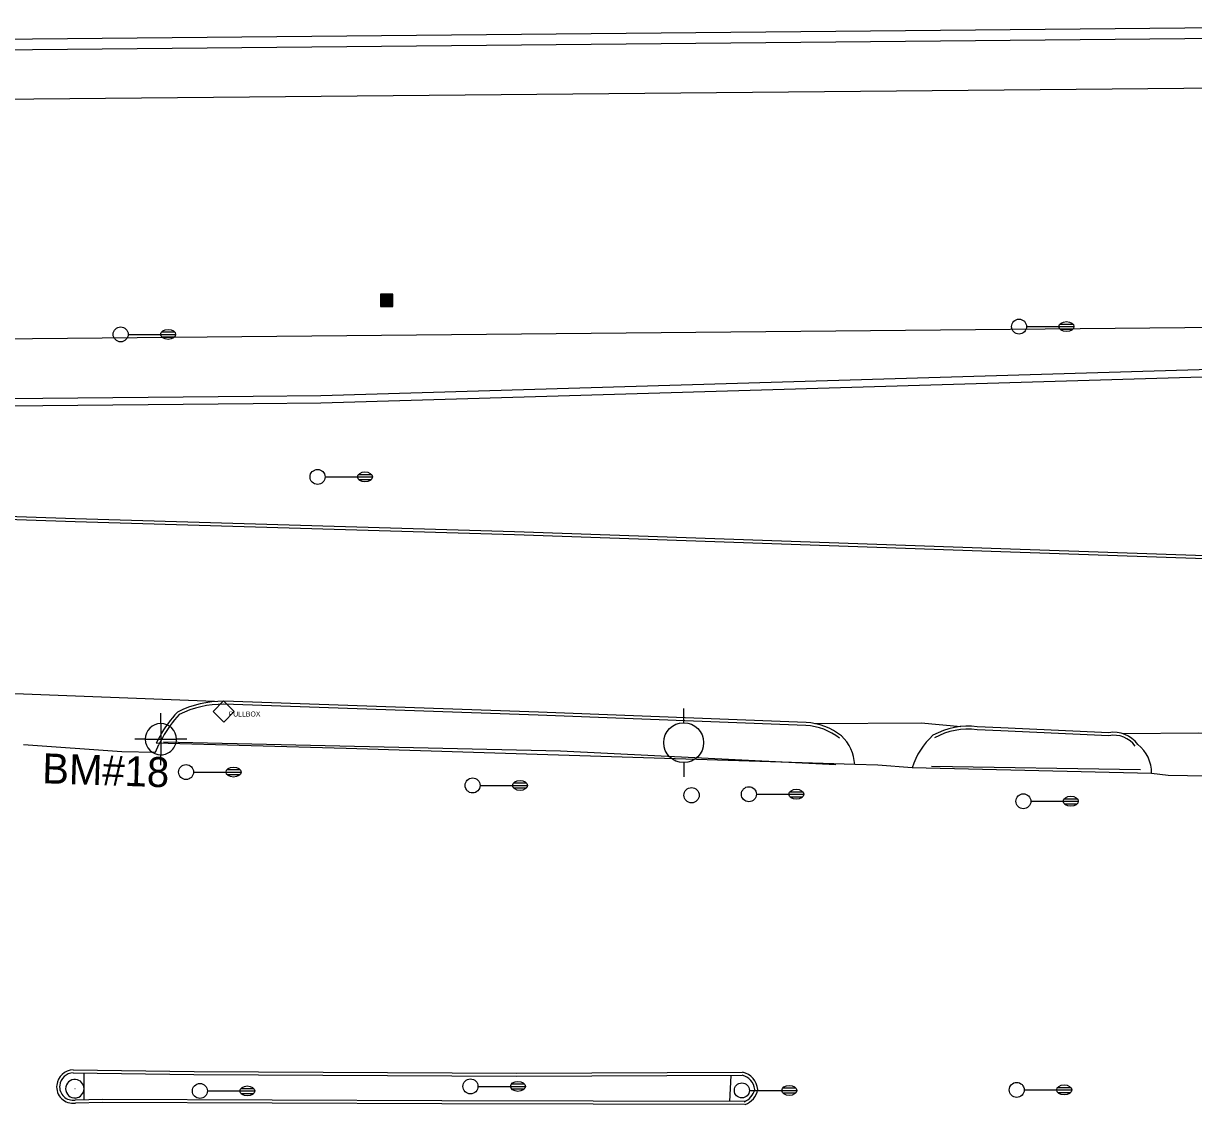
# Model space of a CAD drawing. Extents: x 2145380 to 2157287, y 139568 to 149130.
# Drawn here: x 2146909.1 to 2147143.4, y 142843.8 to 143060.4 of the extents above; entities that cross this region are included whole.
import ezdxf

# ---------------------------------------------------------------- set-up
doc = ezdxf.new("R2010")
doc.units = 0
for name, color, linetype in [('Default', 7, 'Continuous'), ('PR_PREVIOUSLY CONSTRUCTED', 7, 'Continuous'), ('SURV_Benchmark', 7, 'Continuous'), ('TOPO_Asphalt', 7, 'Continuous'), ('TOPO_Concrete', 7, 'Continuous'), ('TOPO_Curb Back', 7, 'Continuous'), ('TOPO_Guardrail', 7, 'Continuous'), ('TOPO_Light Pole', 7, 'Continuous'), ('TOPO_Misc', 7, 'Continuous'), ('TOPO_Power Pole', 7, 'Continuous'), ('TOPO_Power Pullbox', 7, 'Continuous'), ('TOPO_Water Meter', 7, 'Continuous')]:
    doc.layers.add(name, color=color, linetype=linetype)

# ---------------------------------------------------------------- blocks, each defined once
blk = doc.blocks.new('CB')
at = {"layer": 'TOPO_Misc'}
for p, q in [((-3.08, 2.99), (3.24, 2.99)), ((-3.08, 2.68), (3.24, 2.68)), ((-3.08, 2.36), (3.24, 2.36)), ((-3.08, 2.05), (3.24, 2.05)), ((-3.08, 1.73), (3.24, 1.73)), ((-3.08, 1.4), (3.24, 1.4)), ((-3.08, 1.1), (3.24, 1.1)), ((-3.08, 0.77), (3.24, 0.77)), ((-3.08, 0.46), (3.24, 0.46)), ((-3.08, 0.14), (3.24, 0.14)), ((-3.08, -0.17), (3.24, -0.17)), ((-3.08, -0.48), (3.24, -0.48)), ((-3.08, -0.8), (3.24, -0.8)), ((-3.08, -1.11), (3.26, -1.11)), ((-3.08, -1.43), (3.26, -1.43)), ((-3.08, -1.75), (3.26, -1.75)), ((-3.08, -2.07), (3.26, -2.07)), ((-3.08, -2.39), (3.26, -2.39)), ((-3.08, -2.7), (3.26, -2.7)), ((-3.08, -3.02), (3.26, -3.02))]:
    blk.add_line(p, q, dxfattribs=at)
blk.add_lwpolyline([(3.26, -3.29), (3.24, 3.05), (-3.09, 3.04), (-3.08, -3.3), (3.26, -3.29)], dxfattribs=at)
blk = doc.blocks.new('LP')
at = {"layer": 'TOPO_Light Pole'}
blk.add_line((3.81, 0), (20.32, 0), dxfattribs=at)
for points in [[(20.32, 0), (27.94, 0)], [(20.32, 0), (23.5, 0)], [(20.83, 1.27), (27.43, 1.27)], [(20.83, 1.27), (23.5, 1.27)], [(23.71, 1.27), (27.43, 1.27)], [(23.71, 0), (27.94, 0)], [(20.83, -1.27), (27.43, -1.27)], [(20.83, -1.27), (23.5, -1.27)], [(23.71, -1.27), (27.43, -1.27)]]:
    blk.add_lwpolyline(points, dxfattribs=at)
blk.add_circle((0, 0), 3.81, dxfattribs=at)
blk.add_ellipse((24.13, 0), major_axis=(3.81, 0), ratio=0.666667, dxfattribs=at)
blk = doc.blocks.new('POWPOL')
at = {"layer": 'TOPO_Power Pole'}
for p, q in [((0, 10.16), (0, 17.34)), ((0, -10.16), (0, -17.34))]:
    blk.add_line(p, q, dxfattribs=at)
blk.add_circle((0, 0), 10.16, dxfattribs=at)
blk = doc.blocks.new('pulbox')
at = {"layer": 'Default'}
blk.add_lwpolyline([(-5.38, -0.01), (-0.02, 5.42), (5.4, 0.06), (0.05, -5.36), (-5.38, -0.01)], dxfattribs=at)
blk.add_text('PULLBOX', height=2.54, dxfattribs=at).set_placement((2.54, -2.54))
blk = doc.blocks.new('WTRMTR')
at = {"layer": 'Default'}
blk.add_circle((0, 0), 3.89, dxfattribs=at)
blk = doc.blocks.new('BM')
at = {"layer": 'SURV_Benchmark'}
for p, q in [((0, 2.49), (0, 4.15)), ((-2.49, 0), (-4.16, 0)), ((4.16, 0), (2.49, 0)), ((0, -4.16), (0, -2.49))]:
    blk.add_line(p, q, dxfattribs=at)
for points in [[(0, 2.49), (0, 2.49), (0, 0), (2.49, 0), (2.49, 0), (2.49, 0)], [(0, 2.49), (0, 2.49), (0, 0), (2.49, 0), (2.49, 0), (2.49, 0), (2.49, 0)], [(-2.5, 0), (-2.49, 0), (0, 0), (0, -2.49), (0, -2.49)], [(-2.5, 0), (-2.49, 0), (0, 0), (0, -2.49), (0, -2.49)]]:
    blk.add_lwpolyline(points, dxfattribs=at)
for start, end in [(90.0638, 180.0068), (0.0638, 90.0068), (0.0638, 90.0068), (180.0638, 270.0068), (180.0638, 270.0068), (269.9472, 359.9927)]:
    blk.add_arc((0, 0), 2.5, start, end, dxfattribs=at)

msp = doc.modelspace()

# ---------------------------------------------------------------- linework, layer by layer
at = {"layer": 'PR_PREVIOUSLY CONSTRUCTED'}
for p, q in [((2146771.97, 143056.01), (2147234.91, 143060.39)), ((2146771.99, 143053.88), (2147234.93, 143058.27)), ((2146054.19, 143037.14), (2147732.71, 143053.05)), ((2146653.08, 142994.81), (2148008.49, 143007.66))]:
    msp.add_line(p, q, dxfattribs=at)
for points in [[(2148008.6, 142995.66), (2147788.63, 142993.58), (2147488.58, 142996.73), (2147268.56, 142994.65), (2146968.63, 142985.8), (2146955.12, 142985.68), (2146653.19, 142982.81)], [(2147265.03, 142993.04), (2146968.66, 142984.3), (2146955.13, 142984.18), (2146653.2, 142981.31)]]:
    msp.add_lwpolyline(points, dxfattribs=at)
at = {"layer": 'TOPO_Asphalt'}
msp.add_line((2146947.37, 142924.52), (2146896.22, 142926.49), dxfattribs=at)
for points in [[(2147067.59, 142920.13), (2147088.88, 142920.25), (2147096.8, 142919.53)], [(2147075.57, 142911.9), (2147043.9, 142912.93), (2146973.74, 142915.13), (2146935.71, 142916.19)], [(2147129.27, 142918.11), (2147144.44, 142918.24), (2147156.91, 142917.19)], [(2146909.1, 142915.9), (2146928.83, 142914.53), (2146935.54, 142914.42), (2146936.25, 142915.92)], [(2147087.06, 142911.28), (2147080.22, 142911.76), (2147075.57, 142911.9)], [(2147135, 142910.15), (2147087.06, 142911.28)], [(2147146.08, 142909.6), (2147138.37, 142909.71), (2147135, 142910.15)]]:
    msp.add_lwpolyline(points, dxfattribs=at)
for centre, radius, start, end in [((2147067.36, 142911.59), 8.21, 2.1983, 47.5517), ((2147101.38, 142906.65), 15.05, 132.3381, 162.0745), ((2147127.91, 142910.3), 7.1, 358.7645, 52.4035)]:
    msp.add_arc(centre, radius, start, end, dxfattribs=at)
at = {"layer": 'TOPO_Concrete'}
for p, q in [((2146921.25, 142844.73), (2146921.25, 142850.11)), ((2147050.57, 142844.4), (2147050.83, 142849.65))]:
    msp.add_line(p, q, dxfattribs=at)
at = {"layer": 'TOPO_Curb Back'}
for points in [[(2147302.2, 142947.89), (2147268.65, 142949.31), (2147196.44, 142951.96), (2147104.86, 142955.1), (2147007.45, 142958.52), (2146919.46, 142961.11), (2146829.72, 142964.19), (2146749.05, 142964.32), (2146671.05, 142963.99)], [(2147302.21, 142947.29), (2147268.63, 142948.71), (2147196.42, 142951.36), (2147104.83, 142954.5), (2147007.43, 142957.92), (2146919.44, 142960.51), (2146829.71, 142963.59), (2146749.05, 142963.72), (2146671.37, 142963.39)], [(2147065.81, 142919.74), (2147012.19, 142921.79), (2146949.24, 142923.99)], [(2147065.84, 142920.34), (2147012.22, 142922.39), (2146949.25, 142924.59)], [(2147126.49, 142917.69), (2147104.82, 142918.65), (2147100.06, 142918.9)], [(2147126.45, 142918.3), (2147104.85, 142919.25), (2147100.11, 142919.5)], [(2146936.4, 142917.56), (2146935.71, 142916.19)], [(2146936.93, 142917.28), (2146936.25, 142915.92)], [(2146919.09, 142850.73), (2146943.27, 142850.42), (2147007.84, 142850.06), (2147053.13, 142850.26)], [(2146919.1, 142850.13), (2146943.26, 142849.82), (2147007.84, 142849.46), (2147053.06, 142849.66)], [(2147053.51, 142844.39), (2146992.92, 142844.57), (2146924.95, 142844.78), (2146919.45, 142844.7)], [(2147053.5, 142843.79), (2146992.91, 142843.97), (2146924.95, 142844.18), (2146919.51, 142844.11)]]:
    msp.add_lwpolyline(points, dxfattribs=at)
for centre, radius, start, end in [((2146949.07, 142904.1), 20.49, 89.478, 116.4721), ((2146949.07, 142904.1), 19.89, 89.5, 116.1521), ((2146959.07, 142904.89), 25.97, 137.48, 150.8017), ((2146959.07, 142904.89), 25.37, 137.7318, 150.7744), ((2147065.25, 142908.17), 11.58, 51.0762, 87.228), ((2147065.25, 142908.17), 12.18, 51.0762, 87.2425), ((2147098.31, 142905.05), 14.56, 82.8845, 119.0455), ((2147098.31, 142905.05), 13.96, 82.7954, 119.0455), ((2147127.49, 142912.6), 5.79, 34.9864, 100.3823), ((2147127.49, 142912.6), 5.19, 34.9864, 101.1114), ((2146919.14, 142847.35), 3.38, 90.8122, 173.7639), ((2146919.14, 142847.35), 2.78, 90.9726, 173.8329), ((2147052.33, 142846.51), 3.23, 6.012, 76.8575), ((2147052.33, 142846.51), 3.83, 4.6307, 77.955), ((2146919.02, 142847.33), 3.26, 173.125, 278.6358), ((2146919.02, 142847.33), 2.66, 173.0531, 279.4792), ((2147052.27, 142847.51), 3.34, 289.857, 348.5009), ((2147052.27, 142847.51), 3.94, 289.857, 349.8401)]:
    msp.add_arc(centre, radius, start, end, dxfattribs=at)
at = {"layer": 'TOPO_Guardrail'}
msp.add_line((2147090.95, 142911.58), (2147132.81, 142910.95), dxfattribs=at)
msp.add_lwpolyline([(2146937.18, 142916.46), (2147016.66, 142914.65), (2147071.79, 142911.92)], dxfattribs=at)
at = {"layer": 'TOPO_Misc'}
for q in [(2146919.42, 142846.95), (2146919.44, 142846.96), (2146919.44, 142846.93), (2146919.45, 142846.95)]:
    msp.add_line((2146919.44, 142846.95), q, dxfattribs=at)
for centre, radius, start, end in [((2146919.43, 142846.98), 1.87, 85.9623, 180), ((2146919.36, 142846.98), 1.88, 276.2662, 83.7338), ((2146919.43, 142846.98), 1.87, 180, 274.0377)]:
    msp.add_arc(centre, radius, start, end, dxfattribs=at)

# ---------------------------------------------------------------- block references
at = {"layer": 'SURV_Benchmark', "xscale": 1.25, "yscale": 1.25}
msp.add_blockref('BM', (2146936.62, 142916.99), dxfattribs=at)
at = {"layer": 'TOPO_Light Pole', "xscale": 0.39370000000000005, "yscale": 0.3937000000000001}
for p in [(2147108.48, 142999.65), (2146928.58, 142998.1), (2146968, 142969.54), (2146941.68, 142910.41), (2146999.05, 142907.73), (2147054.38, 142905.97), (2147109.34, 142904.56), (2146998.63, 142847.44), (2147108.02, 142846.74), (2146944.44, 142846.52), (2147052.97, 142846.63)]:
    msp.add_blockref('LP', p, dxfattribs=at)
at = {"layer": 'TOPO_Misc', "xscale": 0.39370000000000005, "yscale": 0.3937000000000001}
msp.add_blockref('CB', (2146981.8, 143004.96), dxfattribs=at)
at = {"layer": 'TOPO_Power Pole', "xscale": 0.39370000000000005, "yscale": 0.3937000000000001}
msp.add_blockref('POWPOL', (2147041.32, 142916.3), dxfattribs=at)
at = {"layer": 'TOPO_Power Pullbox', "xscale": 0.39370000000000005, "yscale": 0.3937000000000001}
msp.add_blockref('pulbox', (2146949.2, 142922.54), dxfattribs=at)
at = {"layer": 'TOPO_Water Meter', "xscale": 0.39370000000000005, "yscale": 0.3937000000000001}
msp.add_blockref('WTRMTR', (2147042.9, 142905.77), dxfattribs=at)

# ---------------------------------------------------------------- texts
at = {"layer": 'SURV_Benchmark'}
msp.add_text('BM#18', height=6, rotation=358.1141, dxfattribs=at).set_placement((2146912.8, 142908.18))

doc.saveas('drawing.dxf')
